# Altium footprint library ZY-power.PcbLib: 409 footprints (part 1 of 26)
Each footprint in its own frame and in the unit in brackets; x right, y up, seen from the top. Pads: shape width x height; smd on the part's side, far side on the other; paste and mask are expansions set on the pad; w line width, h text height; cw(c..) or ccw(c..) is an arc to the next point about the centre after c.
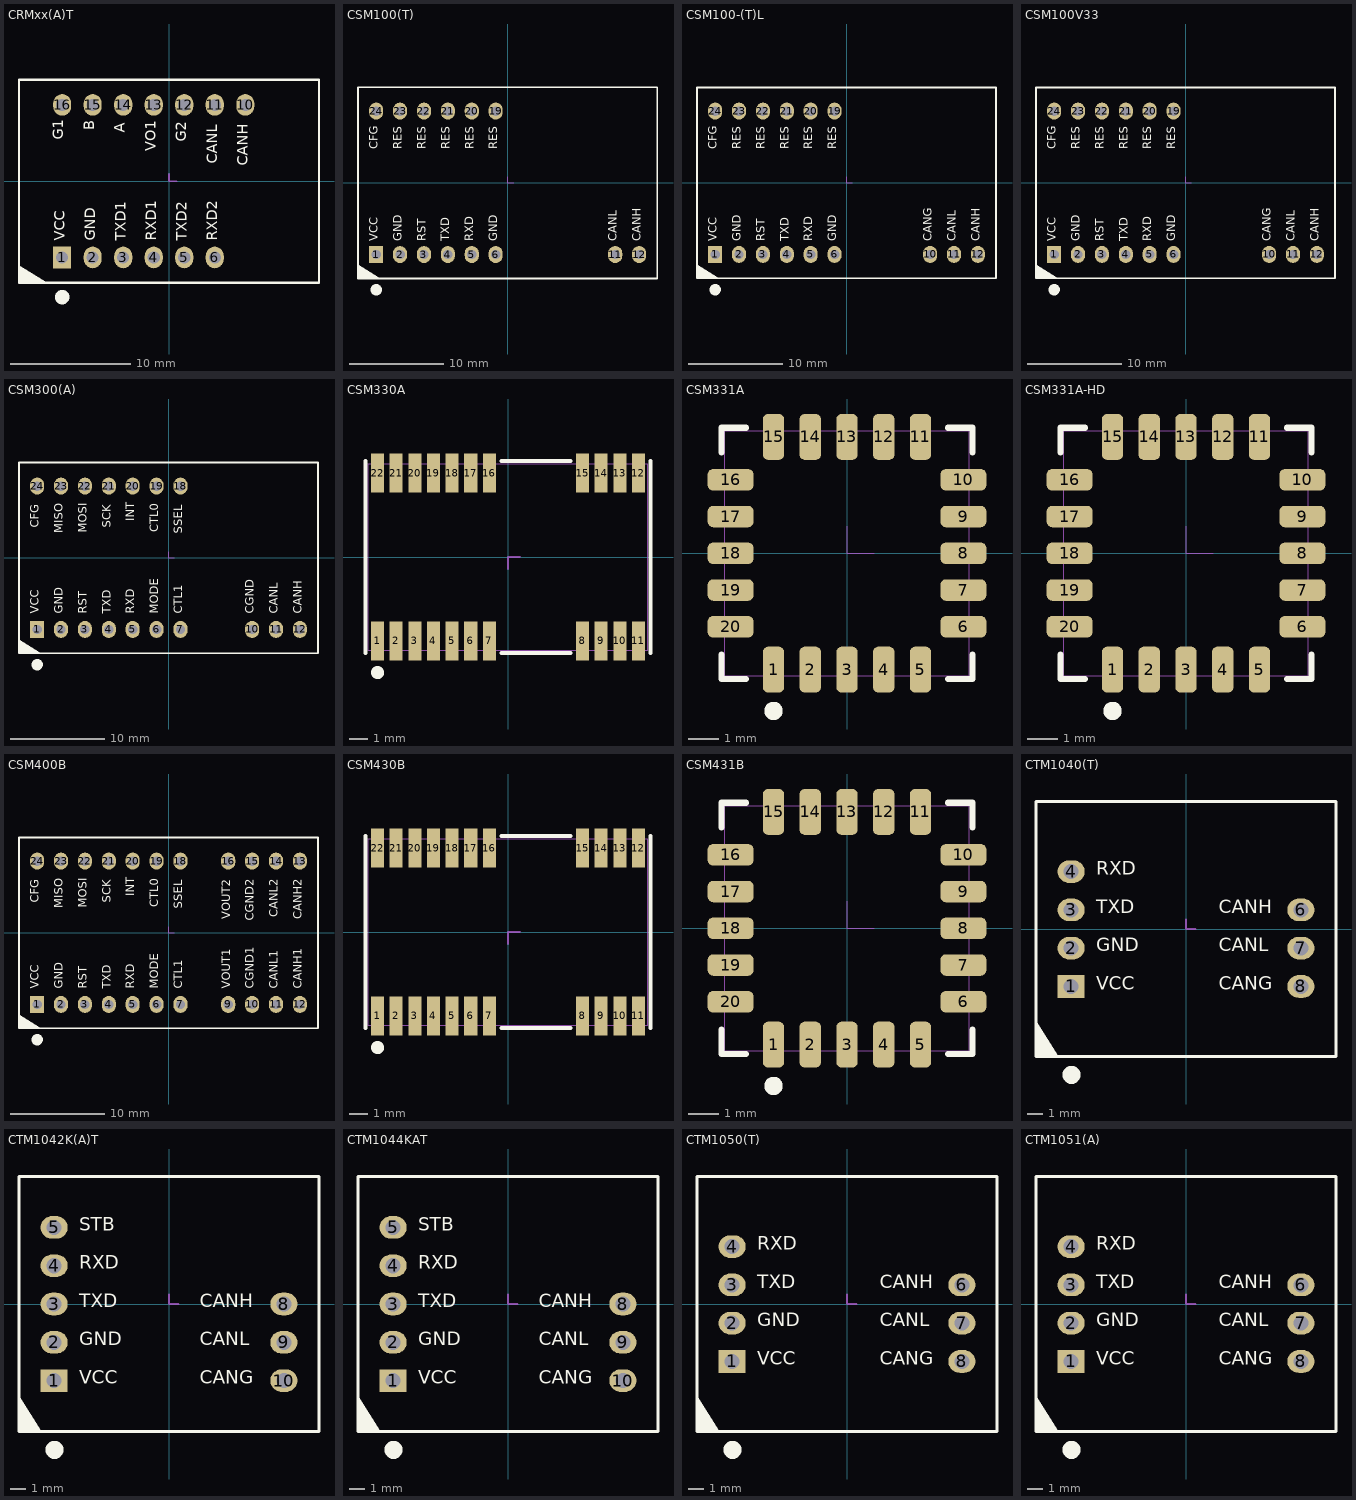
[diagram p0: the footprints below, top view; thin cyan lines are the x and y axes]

## CRMxx(A)T [mm]
height 7.1
pads (13):
  rect 1.5x1.8 hole 1: 1(-8.89,-6.35)
  oval 1.5x1.8 hole 1: 2(-6.35,-6.35) 3(-3.81,-6.35) 4(-1.27,-6.35) 5(1.27,-6.35) 6(3.81,-6.35) 10(6.35,6.35) 11(3.81,6.35) 12(1.27,6.35) 13(-1.27,6.35) 14(-3.81,6.35) 15(-6.35,6.35) 16(-8.89,6.35)
Top Overlay:
  circle w1: c-8.89,-9.649 r0.1
  region: -10.263,-8.45 -12.49,-8.45 -12.49,-6.99 -10.338,-8.338
  lines w0.2: -12.49,-8.45 -12.49,8.45 12.49,8.45 12.49,-8.45 -12.49,-8.45
  text "VCC" at -8.382,-4.953 h1.52
  text "CANH" at 6.858,1.282 h1.52
  text "GND" at -5.842,-4.954 h1.52
  text "TXD1" at -3.302,-4.954 h1.52
  text "RXD1" at -0.762,-4.954 h1.52
  text "TXD2" at 1.778,-4.954 h1.52
  text "RXD2" at 4.318,-4.954 h1.52
  text "CANL" at 4.297,1.446 h1.52
  text "G2" at 1.736,3.29 h1.52
  text "VO1" at -0.826,2.493 h1.52
  text "A" at -3.387,4.053 h1.52
  text "B" at -5.948,4.227 h1.52
  text "G1" at -8.509,3.469 h1.52
Mechanical 15:
  lines w0.127: 0,0.635 0,0 0.635,0

## CSM100(T) [mm] "嵌入式CAN-bus接口芯片"
height 9.4
pads (14):
  rect 1.5x1.8 hole 1: 1(-13.97,-7.62)
  oval 1.5x1.8 hole 1: 2(-11.43,-7.62) 3(-8.89,-7.62) 4(-6.35,-7.62) 5(-3.81,-7.62) 6(-1.27,-7.62) 11(11.43,-7.62) 12(13.97,-7.62) 19(-1.27,7.62) 20(-3.81,7.62) 21(-6.35,7.62) 22(-8.89,7.62) 23(-11.43,7.62) 24(-13.97,7.62)
Top Overlay:
  circle w1: c-13.97,-11.368 r0.1
  region: -13.673,-10.15 -15.9,-10.15 -15.9,-8.69 -13.748,-10.038
  lines w0.2: -15.9,-10.15 -15.9,10.15 15.9,10.15 15.9,-10.15 -15.9,-10.15
  text "CFG" at -13.462,3.556 h1.52
  text "RES" at -8.382,3.556 h1.52
  text "RES" at -5.842,3.556 h1.52
  text "RES" at -3.302,3.556 h1.52
  text "RES" at -0.762,3.556 h1.52
  text "RES" at -10.922,3.556 h1.52
  text "GND" at -0.787,-6.224 h1.52
  text "CANH" at 14.453,-6.224 h1.52
  text "CANL" at 11.913,-6.224 h1.52
  text "RXD" at -3.327,-6.224 h1.52
  text "TXD" at -5.867,-6.224 h1.52
  text "RST" at -8.407,-6.224 h1.52
  text "GND" at -10.947,-6.224 h1.52
  text "VCC" at -13.487,-6.223 h1.52
Mechanical 15:
  lines w0.127: 0,0.635 0,0 0.635,0

## CSM100-(T)L [mm]
pads (15):
  rect 1.5x1.8 hole 1: 1(-13.97,-7.62)
  oval 1.5x1.8 hole 1: 2(-11.43,-7.62) 3(-8.89,-7.62) 4(-6.35,-7.62) 5(-3.81,-7.62) 6(-1.27,-7.62) 10(8.89,-7.62) 11(11.43,-7.62) 12(13.97,-7.62) 19(-1.27,7.62) 20(-3.81,7.62) 21(-6.35,7.62) 22(-8.89,7.62) 23(-11.43,7.62) 24(-13.97,7.62)
Top Overlay:
  circle w1: c-13.97,-11.368 r0.1
  region: -15.9,-10.15 -15.9,-8.69 -13.748,-10.038 -13.589,-10.15
  lines w0.2: -15.9,-10.15 -15.9,10.15 15.9,10.15 15.9,-10.15 -15.9,-10.15
  text "CANG" at 9.398,-6.223 h1.52
  text "CFG" at -13.462,3.556 h1.52
  text "RES" at -8.382,3.556 h1.52
  text "RES" at -5.842,3.556 h1.52
  text "RES" at -3.302,3.556 h1.52
  text "GND" at -0.762,-6.223 h1.52
  text "RES" at -0.762,3.556 h1.52
  text "CANH" at 14.478,-6.223 h1.52
  text "CANL" at 11.938,-6.223 h1.52
  text "RXD" at -3.302,-6.223 h1.52
  text "TXD" at -5.842,-6.223 h1.52
  text "RST" at -8.382,-6.223 h1.52
  text "GND" at -10.922,-6.223 h1.52
  text "VCC" at -13.462,-6.223 h1.52
  text "RES" at -10.922,3.556 h1.52
Mechanical 15:
  lines w0.127: 0,0.635 0,0 0.635,0

## CSM100V33 [mm]
pads (15):
  rect 1.5x1.8 hole 1: 1(-13.97,-7.62)
  oval 1.5x1.8 hole 1: 2(-11.43,-7.62) 3(-8.89,-7.62) 4(-6.35,-7.62) 5(-3.81,-7.62) 6(-1.27,-7.62) 10(8.89,-7.62) 11(11.43,-7.62) 12(13.97,-7.62) 19(-1.27,7.62) 20(-3.81,7.62) 21(-6.35,7.62) 22(-8.89,7.62) 23(-11.43,7.62) 24(-13.97,7.62)
Top Overlay:
  circle w1: c-13.97,-11.368 r0.1
  region: -13.673,-10.15 -15.9,-10.15 -15.9,-8.69 -13.748,-10.038
  lines w0.2: -15.9,-10.15 15.9,-10.15 15.9,10.15 -15.9,10.15 -15.9,-10.15
  text "GND" at -10.922,-6.224 h1.52
  text "TXD" at -5.842,-6.224 h1.52
  text "RXD" at -3.302,-6.224 h1.52
  text "CANL" at 11.938,-6.224 h1.52
  text "CANH" at 14.478,-6.224 h1.52
  text "GND" at -0.762,-6.224 h1.52
  text "CANG" at 9.398,-6.224 h1.52
  text "CFG" at -13.462,3.556 h1.52
  text "RES" at -8.382,3.556 h1.52
  text "RES" at -5.842,3.556 h1.52
  text "RES" at -3.302,3.556 h1.52
  text "RES" at -0.762,3.556 h1.52
  text "RST" at -8.382,-6.224 h1.52
  text "VCC" at -13.462,-6.223 h1.52
  text "RES" at -10.922,3.556 h1.52
Mechanical 15:
  lines w0.127: 0,0.635 0,0 0.635,0

## CSM300(A) [mm]
height 6.5
pads (17):
  rect 1.5x1.8 hole 1: 1(-13.97,-7.62)
  oval 1.5x1.8 hole 1: 2(-11.43,-7.62) 3(-8.89,-7.62) 4(-6.35,-7.62) 5(-3.81,-7.62) 6(-1.27,-7.62) 7(1.27,-7.62) 10(8.89,-7.62) 11(11.43,-7.62) 12(13.97,-7.62) 18(1.27,7.62) 19(-1.27,7.62) 20(-3.81,7.62) 21(-6.35,7.62) 22(-8.89,7.62) 23(-11.43,7.62) 24(-13.97,7.62)
Top Overlay:
  circle w1: c-13.97,-11.368 r0.1
  region: -13.673,-10.15 -15.9,-10.15 -15.9,-8.69 -13.748,-10.038
  lines w0.2: -15.9,-10.15 -15.9,10.15 15.9,10.15 15.9,-10.15 -15.9,-10.15
  text "VCC" at -13.462,-5.969 h1.52
  text "GND" at -10.922,-5.969 h1.52
  text "RST" at -8.382,-5.969 h1.52
  text "TXD" at -5.842,-5.969 h1.52
  text "RXD" at -3.302,-5.969 h1.52
  text "MODE" at -0.762,-5.969 h1.52
  text "CTL1" at 1.778,-5.969 h1.52
  text "CGND" at 9.398,-5.969 h1.52
  text "CANL" at 11.938,-5.969 h1.52
  text "CANH" at 14.478,-5.969 h1.52
  text "CFG" at -13.462,3.192 h1.52
  text "MISO" at -10.922,2.593 h1.52
  text "MOSI" at -8.382,2.654 h1.52
  text "SCK" at -5.842,3.177 h1.52
  text "INT" at -3.302,3.876 h1.52
  text "CTL0" at -0.762,2.717 h1.52
  text "SSEL" at 1.778,2.54 h1.52
Mechanical 15:
  lines w0.127: 0,0.635 0,0 0.635,0
3D body "zhen01.stp": height 6.09, standoff -4.41, extent -14.22,-7.87 -13.72,-7.37
3D body "zhen01.stp": height 6.09, standoff -4.41, extent -11.68,-7.87 -11.18,-7.37
3D body "zhen01.stp": height 6.09, standoff -4.41, extent -9.14,-7.87 -8.64,-7.37
3D body "zhen01.stp": height 6.09, standoff -4.41, extent -6.6,-7.87 -6.1,-7.37
3D body "zhen01.stp": height 6.09, standoff -4.41, extent -4.06,-7.87 -3.56,-7.37
3D body "zhen01.stp": height 6.09, standoff -4.41, extent -1.52,-7.87 -1.02,-7.37
3D body "zhen01.stp": height 6.09, standoff -4.41, extent 1.02,-7.87 1.52,-7.37
3D body "zhen01.stp": height 6.09, standoff -4.41, extent 8.64,-7.87 9.14,-7.37
3D body "zhen01.stp": height 6.09, standoff -4.41, extent 11.18,-7.87 11.68,-7.37
3D body "zhen01.stp": height 6.09, standoff -4.41, extent 13.72,-7.87 14.22,-7.37
3D body "zhen01.stp": height 6.09, standoff -4.41, extent 1.02,7.37 1.52,7.87
3D body "zhen01.stp": height 6.09, standoff -4.41, extent -1.52,7.37 -1.02,7.87
3D body "zhen01.stp": height 6.09, standoff -4.41, extent -4.06,7.37 -3.56,7.87
3D body "zhen01.stp": height 6.09, standoff -4.41, extent -6.6,7.37 -6.1,7.87
3D body "zhen01.stp": height 6.09, standoff -4.41, extent -9.14,7.37 -8.64,7.87
3D body "zhen01.stp": height 6.09, standoff -4.41, extent -11.68,7.37 -11.18,7.87
3D body "zhen01.stp": height 6.09, standoff -4.41, extent -14.22,7.37 -13.72,7.87
3D body: height 6.5, standoff 0, extent -15.9,-10.15 15.9,10.15
3D body: height 6.55, standoff 0, extent -14.732,-8.382 -13.208,-6.858

## CSM330A [mm]
height 3
pads (22):
  rect 0.7x2.1 smd: 1(-7,-4.5) 2(-6,-4.5) 3(-5,-4.5) 4(-4,-4.5) 5(-3,-4.5) 6(-2,-4.5) 7(-1,-4.5) 8(4,-4.5) 9(5,-4.5) 10(6,-4.5) 11(7,-4.5) 12(7,4.5) 13(6,4.5) 14(5,4.5) 15(4,4.5) 16(-1,4.5) 17(-2,4.5) 18(-3,4.5) 19(-4,4.5) 20(-5,4.5) 21(-6,4.5) 22(-7,4.5)
Top Overlay:
  circle w0.5: c-7,-6.2 r0.1
  lines w0.2: -7.65,-5.15 -7.65,5.15 ; -0.35,-5.15 3.35,-5.15 ; -0.35,5.15 3.35,5.15 ; 7.65,-5.15 7.65,5.15
Mechanical 15:
  lines w0.003: -7.5,-5 7.5,-5 7.5,5 -7.5,5 -7.5,-5
  lines w0.127: 0,-0.635 0,0 0.635,0
3D body "CSM330A.stp": height 3.01, standoff -0.01, extent -7.5,-5 7.5,5

## CSM331A [mm]
height 1.17
pads (20):
  rrect50% 0.7x1.5 smd mask+0.102: 1(-2.4,-3.8) 2(-1.2,-3.8) 3(0,-3.8) 4(1.2,-3.8) 5(2.4,-3.8) 11(2.4,3.8) 12(1.2,3.8) 13(0,3.8) 14(-1.2,3.8) 15(-2.4,3.8)
  rrect50% 1.5x0.7 smd mask+0.102: 6(3.8,-2.4) 7(3.8,-1.2) 8(3.8,0) 9(3.8,1.2) 10(3.8,2.4) 16(-3.8,2.4) 17(-3.8,1.2) 18(-3.8,0) 19(-3.8,-1.2) 20(-3.8,-2.4)
Top Overlay:
  circle w0.4: c-2.4,-5.149 r0.1
  circle w0.4: c-2.4,-5.149 r0.1
  circle w0.4: c-2.4,-5.149 r0.1
  lines w0.2: -4.1,-3.3 -4.1,-4.1 -3.3,-4.1 ; -4.1,3.3 -4.1,4.1 -3.3,4.1 ; 3.3,-4.1 4.1,-4.1 4.1,-3.3 ; 3.3,4.1 4.1,4.1 4.1,3.3
Mechanical 13:
  lines w0.013: -4,-4 -4,4 4,4 4,-4 -4,-4
Mechanical 15:
  lines w0.025: 0,0.889 0,0 0.889,0
3D body: height 1.17, standoff 0, extent -4,-4 4,4

## CSM331A-HD [mm]
height 1.17
pads (20):
  rrect50% 0.7x1.5 smd mask+0.102: 1(-2.4,-3.8) 2(-1.2,-3.8) 3(0,-3.8) 4(1.2,-3.8) 5(2.4,-3.8) 11(2.4,3.8) 12(1.2,3.8) 13(0,3.8) 14(-1.2,3.8) 15(-2.4,3.8)
  rrect50% 1.5x0.7 smd mask+0.102: 6(3.8,-2.4) 7(3.8,-1.2) 8(3.8,0) 9(3.8,1.2) 10(3.8,2.4) 16(-3.8,2.4) 17(-3.8,1.2) 18(-3.8,0) 19(-3.8,-1.2) 20(-3.8,-2.4)
Top Overlay:
  circle w0.4: c-2.4,-5.149 r0.1
  circle w0.4: c-2.4,-5.149 r0.1
  circle w0.4: c-2.4,-5.149 r0.1
  lines w0.2: -4.1,-3.3 -4.1,-4.1 -3.3,-4.1 ; -4.1,3.3 -4.1,4.1 -3.3,4.1 ; 3.3,-4.1 4.1,-4.1 4.1,-3.3 ; 3.3,4.1 4.1,4.1 4.1,3.3
Mechanical 13:
  lines w0.013: -4,-4 -4,4 4,4 4,-4 -4,-4
Mechanical 15:
  lines w0.025: 0,0.889 0,0 0.889,0
3D body: height 1.17, standoff 0, extent -4,-4 4,4

## CSM400B [mm]
height 6.5
pads (22):
  rect 1.5x1.8 hole 1: 1(-13.97,-7.62)
  oval 1.5x1.8 hole 1: 2(-11.43,-7.62) 3(-8.89,-7.62) 4(-6.35,-7.62) 5(-3.81,-7.62) 6(-1.27,-7.62) 7(1.27,-7.62) 9(6.35,-7.62) 10(8.89,-7.62) 11(11.43,-7.62) 12(13.97,-7.62) 13(13.97,7.62) 14(11.43,7.62) 15(8.89,7.62) 16(6.35,7.62) 18(1.27,7.62) 19(-1.27,7.62) 20(-3.81,7.62) 21(-6.35,7.62) 22(-8.89,7.62) 23(-11.43,7.62) 24(-13.97,7.62)
Top Overlay:
  circle w1: c-13.97,-11.368 r0.1
  region: -13.673,-10.15 -15.9,-10.15 -15.9,-8.69 -13.748,-10.038
  lines w0.2: -15.9,-10.15 15.9,-10.15 15.9,10.15 -15.9,10.15 -15.9,-10.15
  text "CGND2" at 9.398,1.285 h1.52
  text "CANL2" at 11.938,1.662 h1.52
  text "CANH2" at 14.478,1.436 h1.52
  text "VOUT2" at 6.858,1.449 h1.52
  text "VOUT1" at 6.858,-5.969 h1.52
  text "SSEL" at 1.778,2.54 h1.52
  text "CTL0" at -0.762,2.717 h1.52
  text "INT" at -3.302,3.876 h1.52
  text "SCK" at -5.842,3.177 h1.52
  text "MOSI" at -8.382,2.654 h1.52
  text "MISO" at -10.922,2.593 h1.52
  text "CFG" at -13.462,3.192 h1.52
  text "CANH1" at 14.478,-5.969 h1.52
  text "CANL1" at 11.938,-5.969 h1.52
  text "CGND1" at 9.398,-5.969 h1.52
  text "CTL1" at 1.778,-5.969 h1.52
  text "MODE" at -0.762,-5.969 h1.52
  text "RXD" at -3.302,-5.969 h1.52
  text "TXD" at -5.842,-5.969 h1.52
  text "RST" at -8.382,-5.969 h1.52
  text "GND" at -10.922,-5.969 h1.52
  text "VCC" at -13.462,-5.969 h1.52
Mechanical 15:
  lines w0.127: 0,0.635 0,0 0.635,0
3D body "zhen01.stp": height 6.09, standoff -4.41, extent -14.22,-7.87 -13.72,-7.37
3D body "zhen01.stp": height 6.09, standoff -4.41, extent -11.68,-7.87 -11.18,-7.37
3D body "zhen01.stp": height 6.09, standoff -4.41, extent -9.14,-7.87 -8.64,-7.37
3D body "zhen01.stp": height 6.09, standoff -4.41, extent -6.6,-7.87 -6.1,-7.37
3D body "zhen01.stp": height 6.09, standoff -4.41, extent -4.06,-7.87 -3.56,-7.37
3D body "zhen01.stp": height 6.09, standoff -4.41, extent -1.52,-7.87 -1.02,-7.37
3D body "zhen01.stp": height 6.09, standoff -4.41, extent 1.02,-7.87 1.52,-7.37
3D body "zhen01.stp": height 6.09, standoff -4.41, extent 6.1,-7.87 6.6,-7.37
3D body "zhen01.stp": height 6.09, standoff -4.41, extent 8.64,-7.87 9.14,-7.37
3D body "zhen01.stp": height 6.09, standoff -4.41, extent 11.18,-7.87 11.68,-7.37
3D body "zhen01.stp": height 6.09, standoff -4.41, extent 13.72,-7.87 14.22,-7.37
3D body "zhen01.stp": height 6.09, standoff -4.41, extent 13.72,7.37 14.22,7.87
3D body "zhen01.stp": height 6.09, standoff -4.41, extent 11.18,7.37 11.68,7.87
3D body "zhen01.stp": height 6.09, standoff -4.41, extent 8.64,7.37 9.14,7.87
3D body "zhen01.stp": height 6.09, standoff -4.41, extent 6.1,7.37 6.6,7.87
3D body "zhen01.stp": height 6.09, standoff -4.41, extent 1.02,7.37 1.52,7.87
3D body "zhen01.stp": height 6.09, standoff -4.41, extent -1.52,7.37 -1.02,7.87
3D body "zhen01.stp": height 6.09, standoff -4.41, extent -4.06,7.37 -3.56,7.87
3D body "zhen01.stp": height 6.09, standoff -4.41, extent -6.6,7.37 -6.1,7.87
3D body "zhen01.stp": height 6.09, standoff -4.41, extent -9.14,7.37 -8.64,7.87
3D body "zhen01.stp": height 6.09, standoff -4.41, extent -11.68,7.37 -11.18,7.87
3D body "zhen01.stp": height 6.09, standoff -4.41, extent -14.22,7.37 -13.72,7.87
3D body: height 6.5, standoff 0, extent -15.9,-10.15 15.9,10.15
3D body: height 6.55, standoff 0, extent -14.732,-8.382 -13.208,-6.858

## CSM430B [mm]
height 3
pads (22):
  rect 0.7x2.1 smd: 1(-7,-4.5) 2(-6,-4.5) 3(-5,-4.5) 4(-4,-4.5) 5(-3,-4.5) 6(-2,-4.5) 7(-1,-4.5) 8(4,-4.5) 9(5,-4.5) 10(6,-4.5) 11(7,-4.5) 12(7,4.5) 13(6,4.5) 14(5,4.5) 15(4,4.5) 16(-1,4.5) 17(-2,4.5) 18(-3,4.5) 19(-4,4.5) 20(-5,4.5) 21(-6,4.5) 22(-7,4.5)
Top Overlay:
  circle w0.5: c-7,-6.2 r0.1
  lines w0.2: -7.65,-5.15 -7.65,5.15 ; -0.35,-5.15 3.35,-5.15 ; -0.35,5.15 3.35,5.15 ; 7.65,-5.15 7.65,5.15
Mechanical 15:
  lines w0.003: -7.5,-5 7.5,-5 7.5,5 -7.5,5 -7.5,-5
  lines w0.127: 0,-0.635 0,0 0.635,0
3D body: height 3, standoff 0, extent -7.5,-5 7.5,5

## CSM431B [mm]
height 1
pads (20):
  rrect50% 0.7x1.5 smd mask+0.102: 1(-2.4,-3.8) 2(-1.2,-3.8) 3(0,-3.8) 4(1.2,-3.8) 5(2.4,-3.8) 11(2.4,3.8) 12(1.2,3.8) 13(0,3.8) 14(-1.2,3.8) 15(-2.4,3.8)
  rrect50% 1.5x0.7 smd mask+0.102: 6(3.8,-2.4) 7(3.8,-1.2) 8(3.8,0) 9(3.8,1.2) 10(3.8,2.4) 16(-3.8,2.4) 17(-3.8,1.2) 18(-3.8,0) 19(-3.8,-1.2) 20(-3.8,-2.4)
Top Overlay:
  circle w0.4: c-2.4,-5.149 r0.1
  circle w0.4: c-2.4,-5.149 r0.1
  circle w0.4: c-2.4,-5.149 r0.1
  lines w0.2: -4.1,-3.3 -4.1,-4.1 -3.3,-4.1 ; -4.1,3.3 -4.1,4.1 -3.3,4.1 ; 3.3,-4.1 4.1,-4.1 4.1,-3.3 ; 3.3,4.1 4.1,4.1 4.1,3.3
Mechanical 13:
  lines w0.013: -4,-4 -4,4 4,4 4,-4 -4,-4
Mechanical 15:
  lines w0.025: 0,0.889 0,0 0.889,0
3D body: height 3, standoff 0, extent -4,-4 4,4

## CTM1040(T) [mm]
height 7.1
pads (7):
  rect 1.8x1.5 hole 1: 1(-7.62,-3.81)
  oval 1.8x1.5 hole 1: 2(-7.62,-1.27) 3(-7.62,1.27) 4(-7.62,3.81) 6(7.62,1.27) 7(7.62,-1.27) 8(7.62,-3.81)
Top Overlay:
  circle w1: c-7.593,-9.675 r0.1
  region: -9.95,-6.12 -9.95,-8.45 -8.49,-8.45
  lines w0.2: -9.95,-8.45 -9.95,8.45 9.95,8.45 9.95,-8.45 -9.95,-8.45
  text "VCC" at -5.938,-4.318 h1.52
  text "RXD" at -5.969,3.302 h1.52
  text "TXD" at -5.939,0.762 h1.52
  text "GND" at -5.939,-1.778 h1.52
  text "CANH" at 2.189,0.762 h1.52
  text "CANL" at 2.189,-1.778 h1.52
  text "CANG" at 2.189,-4.318 h1.52
Mechanical 15:
  lines w0.127: 0,0.635 0,0 0.635,0

## CTM1042K(A)T [mm]
height 7.1
pads (8):
  rect 1.8x1.5 hole 1: 1(-7.62,-5.08)
  oval 1.8x1.5 hole 1: 2(-7.62,-2.54) 3(-7.62,0) 4(-7.62,2.54) 5(-7.62,5.08) 8(7.62,0) 9(7.62,-2.54) 10(7.62,-5.08)
Top Overlay:
  circle w1: c-7.593,-9.675 r0.1
  region: -9.95,-6.12 -9.95,-8.45 -8.49,-8.45
  lines w0.2: -9.95,-8.45 -9.95,8.45 9.95,8.45 9.95,-8.45 -9.95,-8.45
  text "CANG" at 2.032,-5.588 h1.52
  text "CANL" at 2.032,-3.048 h1.52
  text "CANH" at 2.032,-0.508 h1.52
  text "STB" at -5.939,4.572 h1.52
  text "RXD" at -5.939,2.032 h1.52
  text "TXD" at -5.939,-0.508 h1.52
  text "VCC" at -5.938,-5.588 h1.52
  text "GND" at -5.939,-3.048 h1.52
Mechanical 15:
  lines w0.127: 0,0.635 0,0 0.635,0

## CTM1044KAT [mm]
height 7.1
pads (8):
  rect 1.8x1.5 hole 1: 1(-7.62,-5.08)
  oval 1.8x1.5 hole 1: 2(-7.62,-2.54) 3(-7.62,0) 4(-7.62,2.54) 5(-7.62,5.08) 8(7.62,0) 9(7.62,-2.54) 10(7.62,-5.08)
Top Overlay:
  circle w1: c-7.593,-9.675 r0.1
  region: -9.95,-6.12 -9.95,-8.45 -8.49,-8.45
  lines w0.2: -9.95,-8.45 9.95,-8.45 9.95,8.45 -9.95,8.45 -9.95,-8.45
  text "GND" at -5.939,-3.048 h1.52
  text "VCC" at -5.938,-5.588 h1.52
  text "TXD" at -5.939,-0.508 h1.52
  text "RXD" at -5.939,2.032 h1.52
  text "STB" at -5.939,4.572 h1.52
  text "CANH" at 2.032,-0.508 h1.52
  text "CANL" at 2.032,-3.048 h1.52
  text "CANG" at 2.032,-5.588 h1.52
Mechanical 15:
  lines w0.127: 0,0.635 0,0 0.635,0
3D body "zhen01.stp": height 6.09, standoff -4.41, extent 7.37,-0.25 7.87,0.25
3D body "zhen01.stp": height 6.09, standoff -4.41, extent 7.37,-2.79 7.87,-2.29
3D body "zhen01.stp": height 6.09, standoff -4.41, extent 7.37,-5.33 7.87,-4.83
3D body "zhen01.stp": height 6.09, standoff -4.41, extent -7.87,4.83 -7.37,5.33
3D body "zhen01.stp": height 6.09, standoff -4.41, extent -7.87,2.29 -7.37,2.79
3D body "zhen01.stp": height 6.09, standoff -4.41, extent -7.87,-0.25 -7.37,0.25
3D body "zhen01.stp": height 6.09, standoff -4.41, extent -7.87,-2.79 -7.37,-2.29
3D body "zhen01.stp": height 6.09, standoff -4.41, extent -7.87,-5.33 -7.37,-4.83
3D body: height 7.3, standoff 0, extent -9.95,-8.45 9.95,8.45

## CTM1050(T) [mm]
height 7.1
pads (7):
  rect 1.8x1.5 hole 1: 1(-7.62,-3.81)
  oval 1.8x1.5 hole 1: 2(-7.62,-1.27) 3(-7.62,1.27) 4(-7.62,3.81) 6(7.62,1.27) 7(7.62,-1.27) 8(7.62,-3.81)
Top Overlay:
  circle w1: c-7.593,-9.675 r0.1
  region: -9.95,-6.12 -9.95,-8.45 -8.49,-8.45
  lines w0.2: -9.95,-8.45 -9.95,8.45 9.95,8.45 9.95,-8.45 -9.95,-8.45
  text "VCC" at -5.938,-4.318 h1.52
  text "RXD" at -5.969,3.302 h1.52
  text "TXD" at -5.939,0.762 h1.52
  text "GND" at -5.939,-1.778 h1.52
  text "CANH" at 2.189,0.762 h1.52
  text "CANL" at 2.189,-1.778 h1.52
  text "CANG" at 2.189,-4.318 h1.52
Mechanical 15:
  lines w0.127: 0,0.635 0,0 0.635,0

## CTM1051(A) [mm]
height 7.1
pads (7):
  rect 1.8x1.5 hole 1: 1(-7.62,-3.81)
  oval 1.8x1.5 hole 1: 2(-7.62,-1.27) 3(-7.62,1.27) 4(-7.62,3.81) 6(7.62,1.27) 7(7.62,-1.27) 8(7.62,-3.81)
Top Overlay:
  circle w1: c-7.593,-9.675 r0.1
  region: -9.95,-6.12 -9.95,-8.45 -8.49,-8.45
  lines w0.2: -9.95,-8.45 -9.95,8.45 9.95,8.45 9.95,-8.45 -9.95,-8.45
  text "VCC" at -5.938,-4.318 h1.52
  text "RXD" at -5.969,3.302 h1.52
  text "TXD" at -5.939,0.762 h1.52
  text "GND" at -5.939,-1.778 h1.52
  text "CANH" at 2.189,0.762 h1.52
  text "CANL" at 2.189,-1.778 h1.52
  text "CANG" at 2.189,-4.318 h1.52
Mechanical 15:
  lines w0.127: 0,0.635 0,0 0.635,0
